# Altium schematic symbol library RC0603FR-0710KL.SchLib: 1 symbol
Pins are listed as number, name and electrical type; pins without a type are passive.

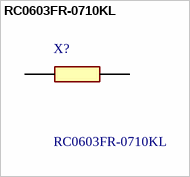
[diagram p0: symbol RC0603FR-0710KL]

## RC0603FR-0710KL
designator X?
Yageo RC Series Thick Film Surface Mount Resistor 0603 Case 10k; Manufacturer_Name: Yageo Group; Geometry.Height: 0.55mm
footprint RESC1608X55N
pins: 1, 2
